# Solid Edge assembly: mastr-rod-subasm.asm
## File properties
Author: Vicky Raina
Template: Normal.asm
Last saved by: MYPC
Revision: 12
Application: Solid Edge
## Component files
master rod.par
piston.par
piston pin.par
piston pin plug.par
piston ring.par
master rod bearing.par
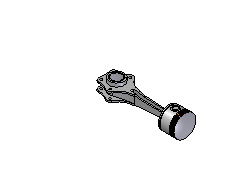
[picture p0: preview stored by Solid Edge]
